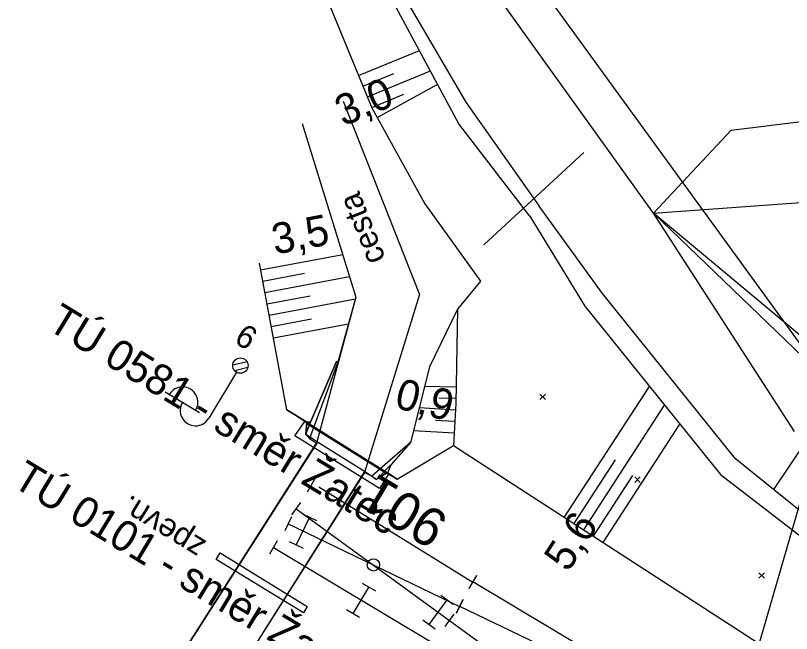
# Model space of a CAD drawing. Extents: x -800194 to -799078, y -1007177 to -1006597.
# Drawn here: x -799838.4 to -799787.9, y -1006953.6 to -1006913.4 of the extents above; entities that cross this region are included whole.
import ezdxf

# ---------------------------------------------------------------- set-up
doc = ezdxf.new("R2010")
doc.units = 0
for name, color, linetype in [('02_Osa_koleje', 7, 'Continuous'), ('_návrh', 7, 'Continuous'), ('Vrstva 16', 7, 'Continuous'), ('Vrstva 17', 7, 'Continuous'), ('Vrstva 18', 7, 'Continuous'), ('Vrstva 2', 7, 'Continuous'), ('Vrstva 25', 7, 'Continuous'), ('Vrstva 3', 7, 'Continuous'), ('Vrstva 45', 7, 'Continuous'), ('Vrstva 48', 7, 'Continuous'), ('Vrstva 49', 7, 'Continuous'), ('Vrstva 51', 7, 'Continuous'), ('Vrstva 55', 7, 'Continuous')]:
    doc.layers.add(name, color=color, linetype=linetype)

msp = doc.modelspace()

# ---------------------------------------------------------------- linework, layer by layer
at = {"layer": '_návrh'}
for p, q in [((-799818.638, -1006944.048), (-799808.621, -1006950.252)), ((-799820.103, -1006945.483), (-799793.935, -1006964.581)), ((-799820.639, -1006946.461), (-799809.505, -1006951.835)), ((-799808.879, -1006950.668), (-799808.365, -1006949.81)), ((-799791.756, -1006960.321), (-799808.622, -1006950.239)), ((-799809.697, -1006952.286), (-799809.264, -1006951.385)), ((-799791.771, -1006960.349), (-799809.481, -1006951.835))]:
    msp.add_line(p, q, dxfattribs=at)
msp.add_lwpolyline([(-799821.595, -1006948.007), (-799811.064, -1006954.324), (-799803.753, -1006958.707), (-799793.935, -1006964.581), (-799784.224, -1006971.671), (-799782.913, -1006972.63), (-799767.418, -1006984.719), (-799752.333, -1006998.173), (-799735.027, -1007015.997), (-799721.623, -1007030.81), (-799713.555, -1007039.726), (-799713.111, -1007040.218)], dxfattribs=at)
at = {"layer": 'Vrstva 16'}
msp.add_lwpolyline([(-799819.635, -1006952.259), (-799825.306, -1006948.779), (-799825.052, -1006948.354), (-799819.395, -1006951.844), (-799819.635, -1006952.259)], dxfattribs=at)
at = {"layer": 'Vrstva 17'}
msp.add_line((-799814.29, -1006943.164), (-799819.456, -1006939.933), dxfattribs=at)
at = {"layer": 'Vrstva 18'}
for p, q in [((-799819.421, -1006939.843), (-799819.489, -1006940.661)), ((-799819.489, -1006940.661), (-799819.417, -1006939.849)), ((-799829.152, -1006957.479), (-799818.799, -1006941.218)), ((-799818.724, -1006941.148), (-799829.145, -1006957.469)), ((-799815.675, -1006943.054), (-799818.724, -1006941.148)), ((-799826.019, -1006959.481), (-799815.665, -1006943.128)), ((-799815.675, -1006943.054), (-799826.005, -1006959.461)), ((-799814.201, -1006943.118), (-799814.895, -1006943.587)), ((-799814.184, -1006943.153), (-799814.895, -1006943.587)), ((-799815.184, -1006943.369), (-799814.895, -1006943.587))]:
    msp.add_line(p, q, dxfattribs=at)
for points in [[(-799817.501, -1006935.902), (-799817.4, -1006935.944), (-799819.236, -1006940.912), (-799818.799, -1006941.218), (-799818.724, -1006941.148), (-799819.489, -1006940.661), (-799819.236, -1006940.912)], [(-799819.489, -1006940.661), (-799819.173, -1006939.861), (-799817.501, -1006935.902)], [(-799819.557, -1006939.811), (-799820.713, -1006939.059), (-799819.421, -1006939.843), (-799819.417, -1006939.849), (-799814.201, -1006943.118)], [(-799814.11, -1006943.242), (-799814.704, -1006944.176), (-799820.193, -1006940.743), (-799819.557, -1006939.811), (-799814.11, -1006943.242)], [(-799812.688, -1006941.178), (-799813.94, -1006942.608), (-799814.895, -1006943.587), (-799815.675, -1006943.054)], [(-799812.688, -1006941.178), (-799815.184, -1006943.369), (-799815.665, -1006943.128), (-799815.675, -1006943.054)], [(-799814.11, -1006943.242), (-799813.557, -1006943.557), (-799813.557, -1006943.559), (-799814.184, -1006943.153), (-799814.201, -1006943.118)]]:
    msp.add_lwpolyline(points, dxfattribs=at)
at = {"layer": 'Vrstva 2'}
for p, q in [((-799819.384, -1006944.384), (-799818.87, -1006943.526)), ((-799820.398, -1006945.887), (-799819.808, -1006945.079)), ((-799820.421, -1006946.011), (-799820.857, -1006946.911)), ((-799821.338, -1006947.578), (-799821.852, -1006948.436)), ((-799808.877, -1006950.681), (-799808.365, -1006949.823)), ((-799809.289, -1006951.384), (-799809.721, -1006952.286)), ((-799810.438, -1006953.151), (-799809.848, -1006952.343))]:
    msp.add_line(p, q, dxfattribs=at)
msp.add_circle((-799815.088, -1006949.141), 0.4, dxfattribs=at)
at = {"layer": 'Vrstva 25'}
for p, q in [((-799823.306, -1006935.918), (-799824.235, -1006936.151)), ((-799823.993, -1006936.599), (-799825.792, -1006939.601)), ((-799823.251, -1006936.29), (-799824.104, -1006936.504)), ((-799826.392, -1006939.242), (-799828.623, -1006937.905))]:
    msp.add_line(p, q, dxfattribs=at)
msp.add_circle((-799823.736, -1006936.17), 0.5, dxfattribs=at)
for centre, start, end in [((-799827.501, -1006938.563), 328.3719, 149.777), ((-799826.65, -1006939.087), 149.0744, 329.0744)]:
    msp.add_arc(centre, 1, start, end, dxfattribs=at)
at = {"layer": 'Vrstva 3'}
for p, q in [((-799819.697, -1006945.807), (-799818.796, -1006946.242)), ((-799819.246, -1006946.024), (-799820.116, -1006947.826)), ((-799820.566, -1006947.608), (-799819.665, -1006948.043)), ((-799815.817, -1006950.316), (-799814.96, -1006950.832)), ((-799815.388, -1006950.574), (-799816.42, -1006952.288)), ((-799810.304, -1006951.393), (-799811.482, -1006953.009)), ((-799810.708, -1006951.098), (-799809.9, -1006951.688)), ((-799816.848, -1006952.03), (-799815.991, -1006952.546)), ((-799811.886, -1006952.714), (-799811.078, -1006953.304))]:
    msp.add_line(p, q, dxfattribs=at)
at = {"layer": 'Vrstva 45'}
msp.add_line((-799807.917, -1006928.309), (-799801.411, -1006922.31), dxfattribs=at)
at = {"layer": 'Vrstva 48'}
for p, q in [((-799816.059, -1006917.301), (-799812.099, -1006915.664)), ((-799815.486, -1006918.687), (-799811.385, -1006916.992)), ((-799815.773, -1006917.994), (-799813.758, -1006917.161)), ((-799814.84, -1006920.039), (-799810.913, -1006917.871)), ((-799815.2, -1006919.38), (-799813.114, -1006918.518)), ((-799822.421, -1006929.94), (-799817.083, -1006928.94)), ((-799822.283, -1006930.677), (-799819.571, -1006930.169)), ((-799822.145, -1006931.414), (-799816.636, -1006930.382)), ((-799822.007, -1006932.151), (-799819.21, -1006931.627)), ((-799821.869, -1006932.888), (-799816.26, -1006931.838)), ((-799821.73, -1006933.625), (-799819.107, -1006933.134)), ((-799821.592, -1006934.363), (-799816.707, -1006933.448)), ((-799809.72, -1006937.564), (-799811.768, -1006937.523)), ((-799802.684, -1006946.043), (-799797.153, -1006937.521)), ((-799809.735, -1006938.314), (-799810.845, -1006938.292)), ((-799801.425, -1006946.86), (-799796.163, -1006938.751)), ((-799809.766, -1006939.063), (-799812.122, -1006938.929)), ((-799809.808, -1006939.812), (-799811.058, -1006939.741)), ((-799800.167, -1006947.676), (-799795.173, -1006939.98)), ((-799809.85, -1006940.56), (-799812.495, -1006940.41)), ((-799786.921, -1006940.996), (-799789.081, -1006944.231)), ((-799802.054, -1006946.452), (-799799.356, -1006942.294)), ((-799800.796, -1006947.268), (-799798.232, -1006943.317))]:
    msp.add_line(p, q, dxfattribs=at)
at = {"layer": 'Vrstva 49'}
for p, q in [((-799796.895, -1006926.253), (-799768.526, -1006924.182)), ((-799787.714, -1006940.466), (-799796.895, -1006926.253)), ((-799777.554, -1006942.387), (-799796.895, -1006926.253)), ((-799809.62, -1006932.499), (-799811.447, -1006936.25)), ((-799804.269, -1006938.024), (-799803.915, -1006938.378)), ((-799804.269, -1006938.378), (-799803.915, -1006938.024)), ((-799813.557, -1006943.557), (-799809.896, -1006941.363)), ((-799798.109, -1006943.418), (-799797.755, -1006943.772)), ((-799798.109, -1006943.772), (-799797.755, -1006943.418)), ((-799790.032, -1006949.644), (-799789.678, -1006949.998)), ((-799790.032, -1006949.998), (-799789.678, -1006949.644))]:
    msp.add_line(p, q, dxfattribs=at)
for points in [[(-799779.16, -1006943.327), (-799796.895, -1006926.253), (-799814.584, -1006901.56)], [(-799816.484, -1006906.344), (-799809.08, -1006919.031), (-799804.329, -1006925.793)], [(-799804.932, -1006926.453), (-799809.531, -1006920.441), (-799816.788, -1006906.944)], [(-799817.932, -1006912.771), (-799815.187, -1006919.411), (-799811.746, -1006925.644), (-799808.124, -1006930.682), (-799809.62, -1006932.499), (-799809.741, -1006938.631), (-799809.896, -1006941.363)], [(-799796.895, -1006926.253), (-799791.85, -1006920.852), (-799769.973, -1006918.145)], [(-799819.72, -1006920.416), (-799816.225, -1006931.712), (-799817.4, -1006935.944), (-799817.501, -1006935.902), (-799819.173, -1006939.861), (-799819.421, -1006939.843), (-799820.713, -1006939.059)], [(-799783.829, -1006948.476), (-799791.557, -1006942.231), (-799800.207, -1006931.486), (-799804.329, -1006925.793)], [(-799804.932, -1006926.453), (-799801.356, -1006932.305), (-799792.538, -1006943.25), (-799784.51, -1006949.428)], [(-799820.713, -1006939.059), (-799822.5, -1006929.516)], [(-799811.447, -1006936.25), (-799812.688, -1006941.178), (-799813.94, -1006942.608), (-799814.184, -1006943.153), (-799813.557, -1006943.559), (-799813.557, -1006943.557)], [(-799809.896, -1006941.363), (-799780.709, -1006960.303)]]:
    msp.add_lwpolyline(points, dxfattribs=at)
at = {"layer": 'Vrstva 51'}
for points in [[(-799817.051, -1006918.973), (-799812.091, -1006931.542), (-799815.665, -1006943.128), (-799826.019, -1006959.481), (-799831.215, -1006965.513), (-799832.478, -1006972.309), (-799831.126, -1006986.858), (-799828.082, -1006983.271), (-799821.896, -1006976.034), (-799813.152, -1006974.923), (-799805.94, -1006982.791), (-799808.362, -1006984.771), (-799815.088, -1006977.554), (-799820.319, -1006978.428), (-799823.433, -1006985.376), (-799830.084, -1006997.726), (-799819.519, -1007011.695), (-799817.354, -1007013.08), (-799784.788, -1007044.956), (-799778.171, -1007047.694), (-799743.858, -1007056.783), (-799726.629, -1007061.89)], [(-799819.72, -1006920.416), (-799816.225, -1006931.712), (-799818.799, -1006941.218), (-799829.152, -1006957.479), (-799833.813, -1006964.907), (-799834.878, -1006971.883), (-799834.851, -1006980.391), (-799838.352, -1006981.216)]]:
    msp.add_lwpolyline(points, dxfattribs=at)
at = {"layer": 'Vrstva 55'}
for points in [[(-799815.49, -1006895.78), (-799807.53, -1006905.17), (-799803.4, -1006912.69), (-799785.23, -1006937.71)], [(-799785.23, -1006937.71), (-799791.69, -1006959.99), (-799791.97, -1006960.97), (-799746.76, -1006987.67), (-799745.68, -1006988.03), (-799733.28, -1006992.13)]]:
    msp.add_lwpolyline(points, dxfattribs=at)

# ---------------------------------------------------------------- texts
at = {"layer": '02_Osa_koleje'}
for s, rotation, p in [('TÚ 0581 - směr Žatec', 328.6802, (-799836.385, -1006933.748)), ('TÚ 0101 - směr Žatec', 328.939, (-799838.658, -1006943.961))]:
    msp.add_text(s, height=2, rotation=rotation, dxfattribs=at).set_placement(p)
at = {"layer": 'Vrstva 16'}
msp.add_text('zpevn.', height=1.5, rotation=148.4647, dxfattribs=at).set_placement((-799825.888, -1006947.616))
at = {"layer": 'Vrstva 2'}
msp.add_text('901', height=2.5, rotation=149.0627, dxfattribs=at).set_placement((-799810.068, -1006946.029))
at = {"layer": 'Vrstva 25'}
msp.add_text('9', height=1.5, rotation=149.0744, dxfattribs=at).set_placement((-799822.483, -1006933.94))
at = {"layer": 'Vrstva 48'}
for s, rotation, p in [('3,0', 22.4604, (-799817.059, -1006920.634)), ('3,5', 10.6062, (-799821.497, -1006928.955)), ('0,9', 345.8653, (-799813.791, -1006938.9)), ('5,6', 57.0197, (-799802.446, -1006949.672))]:
    msp.add_text(s, height=2, rotation=rotation, dxfattribs=at).set_placement(p)
at = {"layer": 'Vrstva 51'}
msp.add_text('cesta', height=1.5, rotation=111.5353, dxfattribs=at).set_placement((-799814.275, -1006929.223))

doc.saveas('drawing.dxf')
